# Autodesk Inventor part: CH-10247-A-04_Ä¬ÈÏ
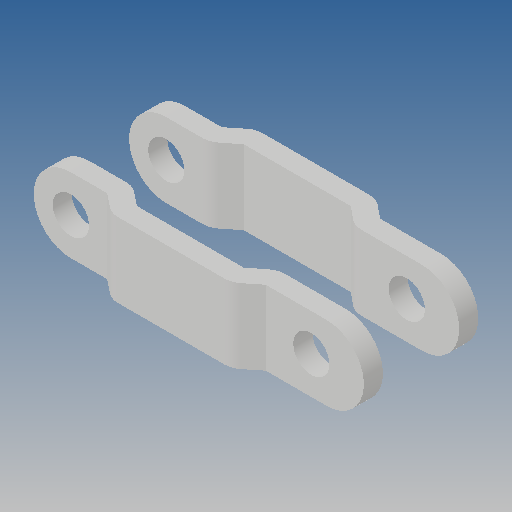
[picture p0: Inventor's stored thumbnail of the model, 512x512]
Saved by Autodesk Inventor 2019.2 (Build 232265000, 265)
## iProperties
Created: 2010-06
Part Number: CH-10247-A-04_Ä¬ÈÏ
Material: Ogólny
Document SubType Name: Modeling
Designer: CADENGINEERING4
Density: 1 g/cm^3
Appearance: Domyślna
Author: CADENGINEERING4
Revision Number: ÈÎºÎ
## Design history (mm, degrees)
feature "NONE"
feature "NONE:1"
node "Bryła1"
node "Bryła2"
